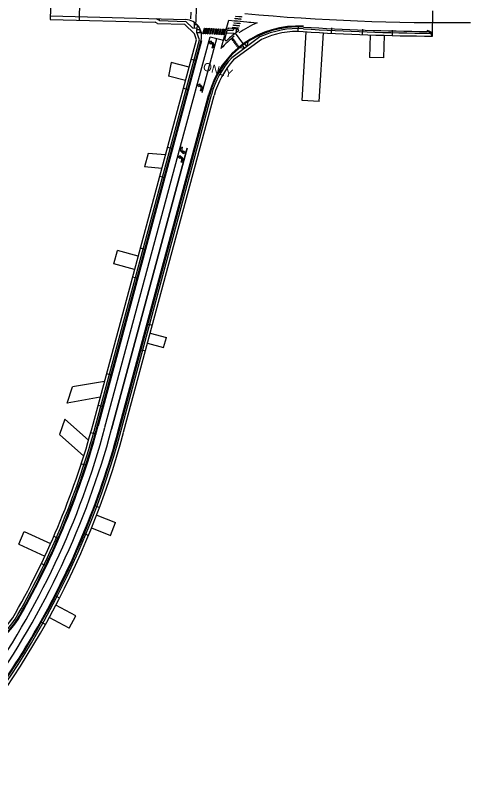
# Model space of a CAD drawing. Extents: x 979036 to 996074, y 1836928 to 1845163.
# Drawn here: x 992377 to 993169, y 1839328 to 1840671 of the extents above; entities that cross this region are included whole.
import ezdxf

# ---------------------------------------------------------------- set-up
doc = ezdxf.new("R2010")
doc.units = 0
for name, color, linetype in [('R_Proposed Road', 7, 'Continuous'), ('STRIPE_White Crosswalk', 7, 'Continuous'), ('STRIPE_White Stopbar', 7, 'Continuous'), ('STRIPE_White Turn Arrow', 7, 'Continuous'), ('STRIPE_White_6in', 7, 'Continuous'), ('STRIPE_White_ONLY', 7, 'Continuous'), ('STRIPE_White_Yield Tri', 7, 'Continuous'), ('STRIPE_Yellow Dbl 6in', 7, 'Continuous'), ('STRIPE_Yellow_10_30 SKIP', 7, 'Continuous'), ('STRIPE_Yellow_45_Diag_8in', 7, 'Continuous')]:
    doc.layers.add(name, color=color, linetype=linetype)

msp = doc.modelspace()

# ---------------------------------------------------------------- linework, layer by layer
at = {"layer": 'R_Proposed Road'}
for p, q in [((992438.5, 1840704.8), (992437.4, 1840664.3)), ((992488.3, 1840695.9), (992487.4, 1840662.9)), ((993102.7, 1840635.2), (993102.9, 1840679.3)), ((992437.4, 1840664.3), (992619.9, 1840659.3)), ((992437.6, 1840670.3), (992673.1, 1840663.8)), ((992627.4, 1840662.1), (992621.5, 1840665.3)), ((992627.4, 1840662.1), (992627.5, 1840665.1)), ((992627.4, 1840662.1), (992673, 1840660.8)), ((992623.9, 1840657.2), (992619.9, 1840659.3)), ((992623.9, 1840657.2), (992670.9, 1840655.9)), ((992688.1, 1840638.9), (992670.9, 1840655.9)), ((992684.6, 1840649.4), (992673, 1840660.8)), ((992684.6, 1840649.4), (992692.6, 1840649.2)), ((992687.8, 1840655.3), (992692.8, 1840655.2)), ((992763.5, 1840647.3), (992748, 1840648.7)), ((992756.5, 1840646.4), (992756.9, 1840647.9)), ((992868.7, 1840643.5), (992869.2, 1840652.7)), ((992926.6, 1840640.1), (992927.1, 1840649.6)), ((992691.7, 1840628.5), (992688.1, 1840638.9)), ((992692.4, 1840641.6), (992692.5, 1840646.6)), ((992692.4, 1840641.6), (992700.1, 1840641.4)), ((992696.9, 1840628.7), (992692.4, 1840641.6)), ((992692.5, 1840646.6), (992698.5, 1840646.4)), ((992698.4, 1840641.4), (992698.5, 1840646.4)), ((992741.2, 1840629.8), (992745.9, 1840647.2)), ((992755.8, 1840639.9), (992744, 1840640.2)), ((992745.3, 1840645.2), (992745.4, 1840645.2)), ((992754.6, 1840644.9), (992745.3, 1840645.2)), ((992757.6, 1840638.7), (992757.4, 1840639.1)), ((992761, 1840643.8), (992762, 1840647.4)), ((992761.6, 1840641.7), (992761.3, 1840642.1)), ((992875.7, 1840523.3), (992882.6, 1840642.6)), ((992905.6, 1840521.5), (992912.6, 1840640.8)), ((992980.5, 1840647.3), (992980.2, 1840637.8)), ((992994.2, 1840637.3), (992993, 1840597.9)), ((993018.2, 1840636.6), (993017, 1840597.2)), ((993032.4, 1840645.7), (993032.1, 1840636.2)), ((992511.8, 1839960.3), (992691.7, 1840628.5)), ((992516.6, 1839959), (992696.9, 1840628.7)), ((992519.5, 1839958.2), (992699.8, 1840627.9)), ((992521, 1839957.8), (992701.2, 1840627.6)), ((992802.3, 1840633.7), (992753.1, 1840597.6)), ((992804.8, 1840629.3), (992756.5, 1840593.8)), ((992779.7, 1840617.1), (992776.1, 1840621.9)), ((992780.9, 1840625.2), (992779.7, 1840617.1)), ((992767.5, 1840615.4), (992775.7, 1840614.1)), ((992775.7, 1840614.1), (992772.1, 1840619)), ((992691.7, 1840591.9), (992682.5, 1840594.4)), ((993017, 1840597.2), (992993, 1840597.9)), ((992647.5, 1840589.3), (992643.2, 1840565.6)), ((992678.8, 1840580.9), (992647.5, 1840589.3)), ((992672.6, 1840557.7), (992643.2, 1840565.6)), ((992678.1, 1840541.7), (992669, 1840544.2)), ((992555.7, 1839948.4), (992713.4, 1840534.3)), ((992557.2, 1839948), (992714.9, 1840533.9)), ((992560.1, 1839947.3), (992717.8, 1840533.1)), ((992564.9, 1839946), (992722.6, 1840531.8)), ((992905.6, 1840521.5), (992875.7, 1840523.3)), ((992641.5, 1840442), (992650.6, 1840439.5)), ((992607.6, 1840431.1), (992601.2, 1840407.6)), ((992637.8, 1840428.5), (992607.6, 1840431.1)), ((992631.5, 1840404.9), (992601.2, 1840407.6)), ((992627.8, 1840391.4), (992637, 1840388.9)), ((992548, 1840239.1), (992554.3, 1840262.3)), ((992590.5, 1840252.5), (992554.3, 1840262.3)), ((992603.3, 1840263.6), (992594.1, 1840266.1)), ((992584.2, 1840229.4), (992548, 1840239.1)), ((992589.8, 1840213.4), (992580.6, 1840215.8)), ((992605.9, 1840134.6), (992615, 1840132.2)), ((992611.4, 1840118.6), (992639.4, 1840111.1)), ((992634.3, 1840093.8), (992639.4, 1840111.1)), ((992606.7, 1840101.3), (992634.5, 1840093.8)), ((992593.9, 1840090.2), (992603.1, 1840087.7)), ((992535.5, 1840048.1), (992544.6, 1840045.7)), ((992531.8, 1840034.6), (992476.3, 1840025.1)), ((992466.5, 1839996.8), (992476.3, 1840025.1)), ((992524.4, 1840006.9), (992466.5, 1839996.8)), ((992520.7, 1839993.4), (992529.9, 1839991)), ((992462.9, 1839969), (992453.7, 1839942.3)), ((992462.9, 1839969), (992504, 1839932.3)), ((992453.7, 1839942.3), (992495.6, 1839904.8)), ((992507.9, 1839945.7), (992517, 1839943)), ((992491.5, 1839891.4), (992500.5, 1839888.6)), ((992514.2, 1839818.6), (992523, 1839815.2)), ((992518.1, 1839802.1), (992551.1, 1839789.1)), ((992542.4, 1839766.7), (992551.1, 1839789.1)), ((992509.3, 1839779.7), (992542.4, 1839766.7)), ((992382.7, 1839751.3), (992392.2, 1839773.4)), ((992392.2, 1839773.4), (992437.9, 1839752.5)), ((992443.6, 1839765.3), (992452.2, 1839761.3)), ((992495.1, 1839770.3), (992504, 1839766.8)), ((992382.7, 1839751.3), (992428, 1839730.6)), ((992422, 1839718), (992430.6, 1839714)), ((992453.4, 1839657.7), (992445.1, 1839662.2)), ((992481.6, 1839626.7), (992447, 1839645.3)), ((992428.8, 1839611.9), (992420.5, 1839616.4)), ((992470.3, 1839605.5), (992435.6, 1839624.1)), ((992470.3, 1839605.5), (992481.6, 1839626.7))]:
    msp.add_line(p, q, dxfattribs=at)
for points in [[(992687.9, 1840659.2), (992687.6, 1840649.3)], [(992687.6, 1840650), (992687.6, 1840649.3)], [(992692.8, 1840655.2), (992692.5, 1840646.6)]]:
    msp.add_lwpolyline(points, dxfattribs=at)
for centre, radius, start, end in [((992672.3, 1840635.4), 28.5, 344.9354, 88.4354), ((992867.9, 1840492.7), 160, 86.363, 164.9354), ((992867.9, 1840492.7), 158.5, 86.363, 164.9354), ((992747.8, 1840646.7), 2, 84.9354, 164.9354), ((993121.3, 1844478.4), 3833.7, 264.9354, 264.9901), ((992867.9, 1840492.7), 155.5, 86.363, 114.9826), ((993121.3, 1844478.4), 3838.2, 266.363, 269.6751), ((993121.3, 1844478.4), 3835.2, 266.363, 269.582), ((992867.9, 1840492.7), 183, 124.4306, 132.4196), ((992754.6, 1840646.9), 2, 268.4354, 344.9354), ((992755.7, 1840637.9), 2, 36.2926, 88.4354), ((992763, 1840643.3), 2, 164.9354, 216.2926), ((992763.3, 1840645.3), 2, 304.4306, 84.9354), ((992867.9, 1840492.7), 150.5, 86.363, 114.7957), ((993121.3, 1844478.4), 3843.2, 266.363, 269.7236), ((993093.2, 1840635.3), 9.5, 359.7236, 89.582), ((993093.2, 1840635.3), 8, 359.7236, 89.582), ((992743.1, 1840629.3), 2, 164.9354, 312.4196), ((992867.9, 1840492.7), 155.5, 137.6025, 164.9354), ((992867.9, 1840492.7), 150.5, 137.7895, 164.9354), ((991155.2, 1840325.4), 1404.9, 330.399, 344.9354), ((991155.2, 1840325.4), 1409.9, 330.399, 344.9354), ((991155.2, 1840325.4), 1412.9, 330.399, 344.9354), ((991155.2, 1840325.4), 1414.4, 330.399, 344.9354), ((991155.2, 1840325.4), 1451.9, 316.9104, 344.9354), ((991155.2, 1840325.4), 1454.9, 316.9104, 344.9354), ((991155.2, 1840325.4), 1459.9, 316.9104, 344.9354), ((991155.2, 1840325.4), 1450.4, 329.8678, 344.9354), ((992254.6, 1839700.8), 148.5, 289.5442, 330.399), ((992254.6, 1839700.8), 140.5, 300.4844, 330.399), ((992254.6, 1839700.8), 145.5, 300.2773, 330.399), ((992254.6, 1839700.8), 150, 287.6246, 330.399), ((991155.2, 1840325.4), 1450.4, 316.9104, 329.8678)]:
    msp.add_arc(centre, radius, start, end, dxfattribs=at)
at = {"layer": 'STRIPE_White Crosswalk'}
for p, q in [((992691.2, 1840687.3), (992690.4, 1840659.5)), ((992772.5, 1840622.7), (992759.8, 1840640.3))]:
    msp.add_line(p, q, dxfattribs=at)
for points in [[(992768.2, 1840661.4), (992768.1, 1840660.4), (992758.1, 1840661.3), (992758.2, 1840662.3)], [(992769.2, 1840665.2), (992769.1, 1840664.2), (992759.2, 1840665.1), (992759.3, 1840666.1)], [(992770.3, 1840669.1), (992770.2, 1840668.1), (992760.2, 1840669), (992760.3, 1840670)], [(992705.5, 1840649.1), (992706.5, 1840648.8), (992703.9, 1840639.1), (992702.9, 1840639.4)], [(992709.5, 1840648.9), (992710.4, 1840648.6), (992707.8, 1840639), (992706.9, 1840639.2)], [(992713.5, 1840648.7), (992714.4, 1840648.4), (992711.8, 1840638.8), (992710.9, 1840639)], [(992717.5, 1840648.5), (992718.4, 1840648.2), (992715.8, 1840638.6), (992714.9, 1840638.8)], [(992721.5, 1840648.2), (992722.4, 1840647.9), (992719.8, 1840638.3), (992718.9, 1840638.5)], [(992725.5, 1840648.1), (992726.4, 1840647.9), (992723.8, 1840638.2), (992722.9, 1840638.5)], [(992729.5, 1840647.9), (992730.4, 1840647.7), (992727.8, 1840638), (992726.9, 1840638.3)], [(992733.5, 1840647.8), (992734.4, 1840647.5), (992731.8, 1840637.8), (992730.9, 1840638.1)], [(992765.1, 1840649.8), (992765, 1840648.8), (992755, 1840649.7), (992755.1, 1840650.7)], [(992766.1, 1840653.6), (992766, 1840652.7), (992756, 1840653.5), (992756.1, 1840654.5)], [(992767.1, 1840657.5), (992767, 1840656.5), (992757.1, 1840657.4), (992757.2, 1840658.4)], [(992737.5, 1840647.6), (992738.4, 1840647.3), (992735.8, 1840637.6), (992734.9, 1840637.9)], [(992741.4, 1840647.4), (992742.4, 1840647.1), (992739.8, 1840637.5), (992738.8, 1840637.7)]]:
    msp.add_lwpolyline(points, close=True, dxfattribs=at)
at = {"layer": 'STRIPE_White Stopbar'}
for p, q in [((992681.9, 1840677.1), (992681.5, 1840665.1)), ((992715.4, 1840634.1), (992738.6, 1840627.9))]:
    msp.add_line(p, q, dxfattribs=at)
at = {"layer": 'STRIPE_White Turn Arrow'}
for points in [[(992716.8, 1840621.4), (992713.8, 1840624.6), (992717.6, 1840626.7), (992717.4, 1840625.1), (992718, 1840624.9), (992718.5, 1840624.7), (992719.3, 1840624.3), (992720.1, 1840623.8), (992720.7, 1840623.2), (992721.1, 1840622.5), (992721.6, 1840621.7), (992721.9, 1840620.9), (992722.1, 1840620.1), (992722.1, 1840619.1), (992722, 1840618.1), (992720.9, 1840614.4), (992719, 1840614.9), (992720, 1840618.4), (992720.1, 1840619.1), (992720.1, 1840619.8), (992719.9, 1840620.7), (992719.5, 1840621.4), (992719.3, 1840621.7), (992718.8, 1840622.3), (992718.1, 1840622.7), (992717.4, 1840623), (992717, 1840623.1)], [(992696.7, 1840546.7), (992693.7, 1840549.9), (992697.5, 1840552), (992697.2, 1840550.4), (992697.9, 1840550.2), (992698.4, 1840550), (992699.2, 1840549.6), (992700, 1840549.1), (992700.6, 1840548.5), (992701, 1840547.8), (992701.5, 1840547), (992701.7, 1840546.2), (992702, 1840545.4), (992702, 1840544.4), (992701.9, 1840543.4), (992700.8, 1840539.7), (992698.9, 1840540.2), (992699.8, 1840543.7), (992700, 1840544.4), (992699.9, 1840545.1), (992699.8, 1840546), (992699.4, 1840546.7), (992699.2, 1840547), (992698.7, 1840547.6), (992698, 1840548), (992697.3, 1840548.3), (992696.9, 1840548.4)], [(992669.5, 1840435.5), (992672.6, 1840432.5), (992668.9, 1840430.2), (992669.1, 1840431.9), (992668.4, 1840432), (992667.9, 1840432.2), (992667.1, 1840432.5), (992666.3, 1840433.1), (992665.6, 1840433.6), (992665.2, 1840434.3), (992664.6, 1840435), (992664.4, 1840435.8), (992664.1, 1840436.6), (992664, 1840437.6), (992664.1, 1840438.6), (992665, 1840442.4), (992666.9, 1840441.9), (992666.2, 1840438.4), (992666.1, 1840437.7), (992666.1, 1840437), (992666.3, 1840436.1), (992666.8, 1840435.4), (992667, 1840435.1), (992667.5, 1840434.6), (992668.2, 1840434.2), (992668.9, 1840434), (992669.3, 1840433.9)], [(992662.8, 1840422.4), (992659.7, 1840425.4), (992663.4, 1840427.7), (992663.2, 1840426), (992663.9, 1840425.9), (992664.4, 1840425.7), (992665.2, 1840425.4), (992666, 1840424.9), (992666.7, 1840424.3), (992667.1, 1840423.7), (992667.7, 1840422.9), (992667.9, 1840422.2), (992668.2, 1840421.3), (992668.3, 1840420.4), (992668.2, 1840419.4), (992667.4, 1840415.6), (992665.4, 1840416), (992666.2, 1840419.5), (992666.3, 1840420.2), (992666.2, 1840421), (992666, 1840421.8), (992665.6, 1840422.5), (992665.3, 1840422.8), (992664.8, 1840423.3), (992664.1, 1840423.7), (992663.4, 1840424), (992663, 1840424)]]:
    msp.add_lwpolyline(points, close=True, dxfattribs=at)
at = {"layer": 'STRIPE_White_6in'}
for p, q in [((992743.7, 1840646.8), (992748, 1840662.7)), ((992748, 1840662.7), (992758.2, 1840661.8)), ((992768.1, 1840660.9), (992797.5, 1840658.3)), ((992734.9, 1840613.9), (992741.1, 1840637.1)), ((992701.7, 1840537), (992727, 1840631))]:
    msp.add_line(p, q, dxfattribs=at)
for start, end in [(113.0506, 124.6531), (127.8135, 137.6693)]:
    msp.add_arc((992867.9, 1840492.7), 180, start, end, dxfattribs=at)
at = {"layer": 'STRIPE_White_Yield Tri'}
for p, q in [((992754.3, 1840632.3), (992752.4, 1840629.8)), ((992752.4, 1840629.8), (992755.4, 1840630.7)), ((992756, 1840629.9), (992754.2, 1840627.3)), ((992754.2, 1840627.3), (992757.2, 1840628.3)), ((992755.4, 1840630.7), (992754.3, 1840632.3)), ((992757.2, 1840628.3), (992756, 1840629.9)), ((992757.8, 1840627.5), (992756, 1840624.9)), ((992756, 1840624.9), (992759, 1840625.8)), ((992759.6, 1840625), (992757.7, 1840622.5)), ((992757.7, 1840622.5), (992760.8, 1840623.4)), ((992759, 1840625.8), (992757.8, 1840627.5)), ((992761.4, 1840622.6), (992759.5, 1840620.1)), ((992759.5, 1840620.1), (992762.6, 1840621)), ((992760.8, 1840623.4), (992759.6, 1840625)), ((992762.6, 1840621), (992761.4, 1840622.6)), ((992763.1, 1840620.2), (992761.3, 1840617.7)), ((992761.3, 1840617.7), (992764.3, 1840618.6)), ((992764.3, 1840618.6), (992763.1, 1840620.2)), ((992764.9, 1840617.8), (992763.1, 1840615.3)), ((992763.1, 1840615.3), (992766.1, 1840616.2)), ((992766.1, 1840616.2), (992764.9, 1840617.8))]:
    msp.add_line(p, q, dxfattribs=at)
at = {"layer": 'STRIPE_Yellow Dbl 6in'}
msp.add_line((992664.2, 1840443.6), (992715.4, 1840634.1), dxfattribs=at)
msp.add_arc((993121.3, 1844478.4), 3819.7, 264.8133, 270.7131, dxfattribs=at)
at = {"layer": 'STRIPE_Yellow_10_30 SKIP'}
for p, q in [((992532.6, 1839954.7), (992664.2, 1840443.6)), ((992532.6, 1839954.7), (992664.2, 1840443.6)), ((992544.2, 1839951.6), (992675.7, 1840440.4)), ((992675.7, 1840440.4), (992544.2, 1839951.6))]:
    msp.add_line(p, q, dxfattribs=at)
for radius in [1426.4, 1426.4, 1438.4, 1438.4]:
    msp.add_arc((991155.2, 1840325.4), radius, 324.6947, 344.9354, dxfattribs=at)
at = {"layer": 'STRIPE_Yellow_45_Diag_8in'}
msp.add_line((992676.3, 1840487.3), (992676.4, 1840487.3), dxfattribs=at)

# ---------------------------------------------------------------- texts
at = {"layer": 'STRIPE_White_ONLY'}
msp.add_text('ONLY', height=14.4, rotation=344.9354, dxfattribs=at).set_placement((992702, 1840576))

doc.saveas('drawing.dxf')
